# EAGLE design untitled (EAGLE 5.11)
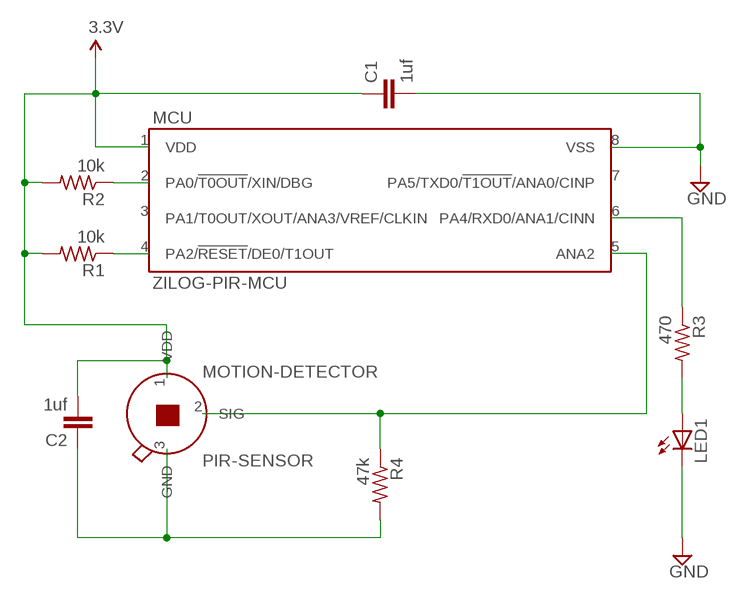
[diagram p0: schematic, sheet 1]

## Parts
C1  1uf  C-EUC1206  [C1206]
C2  1uf  C-EUC1206  [C1206]
LED1  LEDCHIP-LED0805  [CHIP-LED0805]
MCU  ZILOG-PIR-MCU  [8SOIC]
MOTION-DETECTOR  PIR-SENSOR  [PIR-SENSOR-TO-18V-MOD]
R1  10k  R-US_R1210  [R1210]
R2  10k  R-US_R1210  [R1210]
R3  470  R-US_R1206  [R1206]
R4  47k  R-US_R1206  [R1206]

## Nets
3.3V: C1.1 C2.2 MCU.1(VDD) MOTION-DETECTOR.1(VDD) R1.2 R2.2
GND: C1.2 LED1.C MCU.8(VSS)
N$1: MCU.4(PA2/!RESET!/DE0/T1OUT) R1.1
N$2: LED1.A R3.2
N$3: MCU.2(PA0/!T0OUT!/XIN/DBG) R2.1
N$4: MCU.6(PA4/RXD0/ANA1/CINN) R3.1
N$5: MCU.5(ANA2) MOTION-DETECTOR.2(SIG) R4.1
N$6: C2.1 MOTION-DETECTOR.3(GND) R4.2
Unconnected: MCU.3(PA1/T0OUT/XOUT/ANA3/VREF/CLKIN) MCU.7(PA5/TXD0/!T1OUT!/ANA0/CINP)

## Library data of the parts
C1 C2 = rcl:C-EU: CAPACITOR, European symbol
LED1 = led:LED: LED
MCU = trl:ZILOG-PIR-MCU
MOTION-DETECTOR = trl:PIR-SENSOR
R1-R4 = resistor:R-US_: RESISTOR, American symbol

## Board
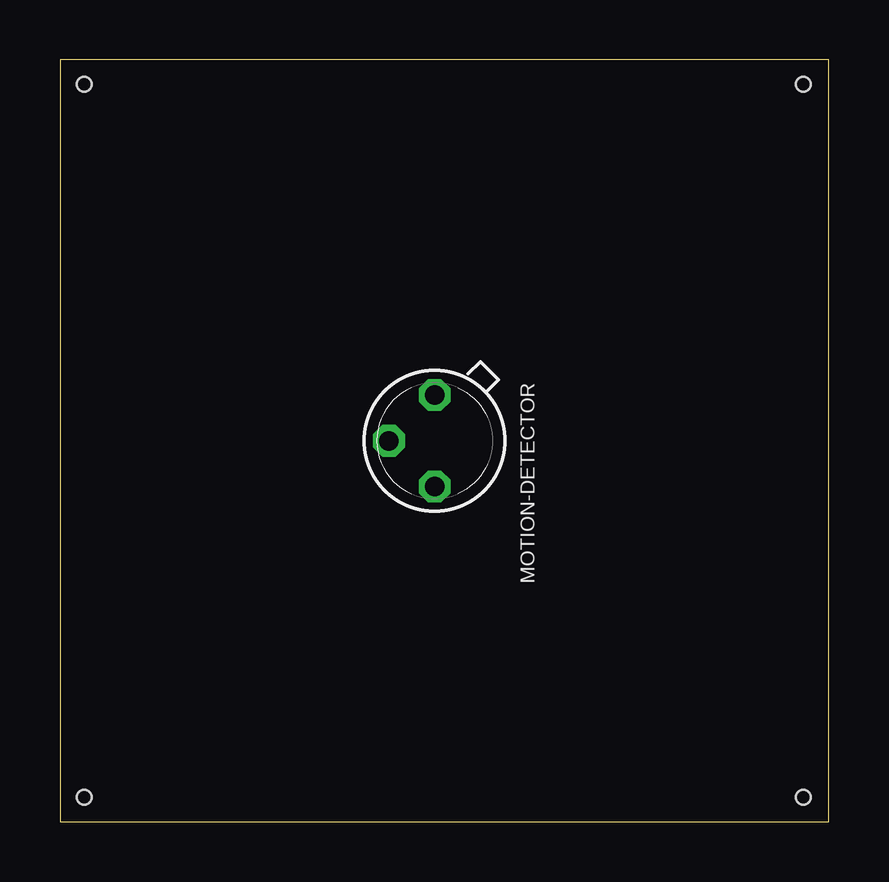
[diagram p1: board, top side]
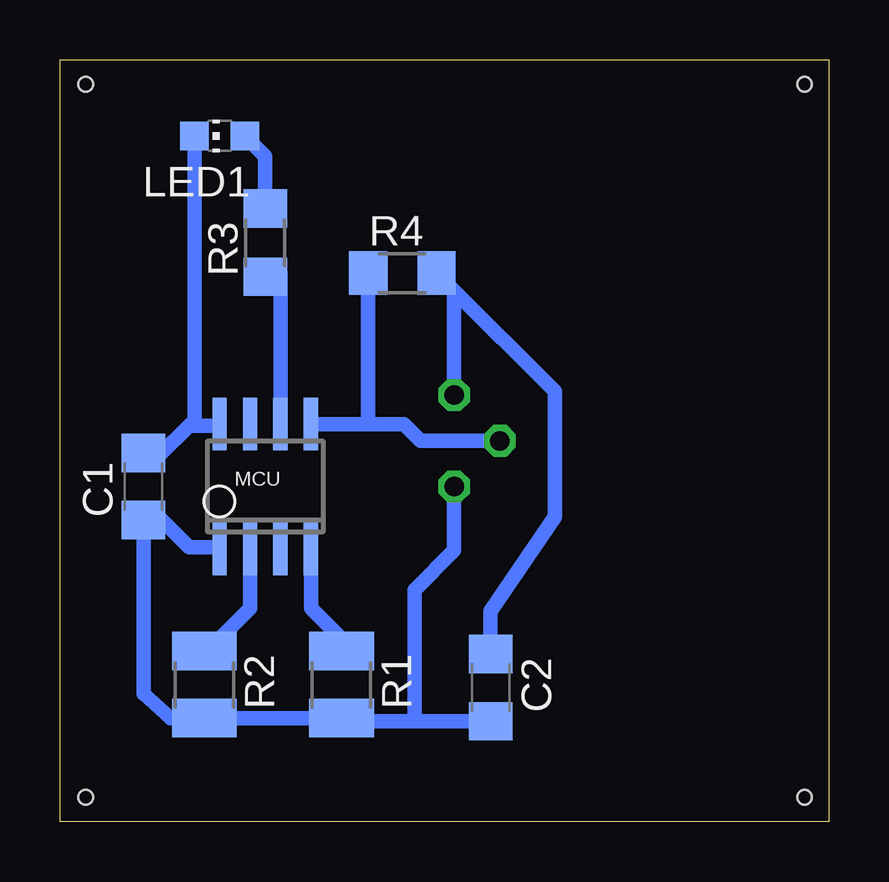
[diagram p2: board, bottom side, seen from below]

Size 32.05 x 31.74 mm. Coordinates in mm from the lower left corner, seen from the top.
Outline: 0,0 32.05,0 32.05,31.74 0,31.74 0,0
Copper layers (1*16): Top 0.035mm / dielectric 1.5mm / Bottom 0.035mm
Design rules "default": minimum track width 10mil, minimum drill 24mil, track to track 8mil, track to pad 8mil, pad to pad 8mil, via to via 8mil, smd to smd 8mil, copper to edge 40mil, drill to drill 8mil, minimum pad ring 10mil, minimum via ring 8mil, stop-mask expansion 4mil, vias tented up to drill 0mil, thermal gap 10mil
Holes 0.6 mm at 1.02,30.73 1.02,1.02 30.99,1.02 30.99,30.73

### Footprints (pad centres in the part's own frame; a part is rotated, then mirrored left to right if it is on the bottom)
C1206 = smd 1.6 x 1.8: 1 -1.4,0; 2 1.4,0
CHIP-LED0805 = smd 1.2 x 1.2: A 0,-1.05; C 0,1.05
8SOIC = smd 0.6 x 2.2: 1 -1.905,-2.6; 2 -0.635,-2.6; 3 0.635,-2.6; 4 1.905,-2.6; 5 1.905,2.6; 6 0.635,2.6; 7 -0.635,2.6; 8 -1.905,2.6
PIR-SENSOR-TO-18V-MOD = drill 0.813 octagon: 1 1.905,0; 2 0,-1.905; 3 -1.905,0
R1210 = smd 1.6 x 2.7: 1 -1.4,0; 2 1.4,0
R1206 = smd 1.6 x 1.803: 1 -1.422,0; 2 1.422,0

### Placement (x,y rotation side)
C1  28.57,13.97 90 bottom
C2  14.1,5.59 270 bottom
LED1  25.4,28.57 90 bottom
MCU  23.5,13.97 0 bottom
MOTION-DETECTOR  15.62,15.88 270 top
R1  20.32,5.71 270 bottom
R2  26.04,5.71 270 bottom
R3  23.5,24.13 90 bottom
R4  17.78,22.86 0 bottom

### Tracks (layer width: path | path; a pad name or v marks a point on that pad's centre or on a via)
3.3V
  Bottom 0.254: 25.4,11.43 MCU.1
  Bottom 0.61: 25.4,11.43 26.67,11.43 27.94,12.7 C1.1 28.57,12.32 28.57,5.33 27.43,4.32 R2.2 R1.2 20.19,4.19 17.27,4.19 | C2.2 17.27,4.19 | MOTION-DETECTOR.1 15.62,11.3 17.27,9.65 17.27,4.19
GND
  Bottom 0.254: 27.94,15.24 C1.2 | MCU.8 25.4,16.51
  Bottom 0.61: 26.67,16.51 27.94,15.24 | 25.4,16.51 26.67,16.51 | LED1.C 26.45,16.73 26.67,16.51
N$1
  Bottom 0.254: R1.1 20.32,7.62 | MCU.4 21.59,11.43 MCU.4
  Bottom 0.61: MCU.4 21.59,8.89 20.32,7.62
N$2
  Bottom 0.61: R3.2 23.5,27.72 LED1.A
N$3
  Bottom 0.254: R2.1 25.4,7.62 | MCU.2 24.13,11.43 MCU.2
  Bottom 0.61: MCU.2 24.13,8.89 25.4,7.62
N$4
  Bottom 0.254: MCU.6 22.86,16.51 MCU.6
  Bottom 0.61: MCU.6 22.86,22.86 R3.1
N$5
  Bottom 0.61: 19.05,16.57 17.71,16.57 17.02,15.88 MOTION-DETECTOR.2 | 19.05,16.57 MCU.5 | R4.1 19.2,16.72 19.05,16.57
N$6
  Bottom 0.61: MOTION-DETECTOR.3 15.62,22.12 15.8,22.3 | 15.8,22.3 R4.2 | C2.1 14.1,8.76 11.43,12.7 11.43,16.51 11.43,17.93 15.8,22.3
